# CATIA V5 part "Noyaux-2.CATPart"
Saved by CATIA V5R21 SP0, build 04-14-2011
Part number: Noyaux
Bounding box of the stored display mesh (mm): x -7.25 to 7.25, y -70.25 to 67.25, z -7.25 to 7.25
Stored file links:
  C:\Users\zerma\Pictures\Moule\Noyaux-2.CATPart
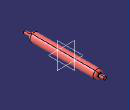
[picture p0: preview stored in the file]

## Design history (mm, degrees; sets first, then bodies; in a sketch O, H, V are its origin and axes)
Body1 (main body)
  DatumCurve1 "Longueur_moule"
  DatumCurve2
  DatumCurve3
  Sketch1 on yz-plane, origin (0, 0, 0), H (0, 1, 0), V (0, 0, 1)
    point P1 (58.25, 7.25)
    point P2 (0, 0)
    line L1 (67.25, 0) -> (67.25, 2.5)
    line L2 (67.25, 2.5) -> (58.25, 2.5)
    point P5 (58.25, 2.5)
    line L3 (58.25, 7.25) -> (58.25, 2.5)
    point P6 (-58.25, 7.25)
    line L4 (-58.25, 7.25) -> (58.25, 7.25)
    line L5 (67.25, 0) -> (-70.25, 0)
    point P8 (-58.25, 2.5)
    point P9 (-58.25, 7.25)
    line L6 (-58.25, 7.25) -> (-58.25, 2.5)
    line L7 (-70.25, 0) -> (-70.25, 2.5)
    line L8 (-58.25, 2.5) -> (-70.25, 2.5)
    length L2 = 9
    length L1 = 2.5
    length L4 = 116.5
    length L8 = 12
    distance L4 L5 = 7.25
    vertical: L1 V, L3 V, L7 V
    horizontal: L2 H, L4 H, L5 H, L8 H
    coincidence: P2 O, L5 H
    symmetry: P1 P6 V, P5 P8 V, P1 P9 V, L3 L6 V
  Shaft1: profile Sketch1, axis Sketch1.L5, angle 360
  Fillet1: radius 4, on edge [face of Shaft1 from Sketch1.L4 | face of Shaft1 from Sketch1.L3]; edge [face of Shaft1 from Sketch1.L6 | face of Shaft1 from Sketch1.L4]
  CLDGeom1 "Maillage.1"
